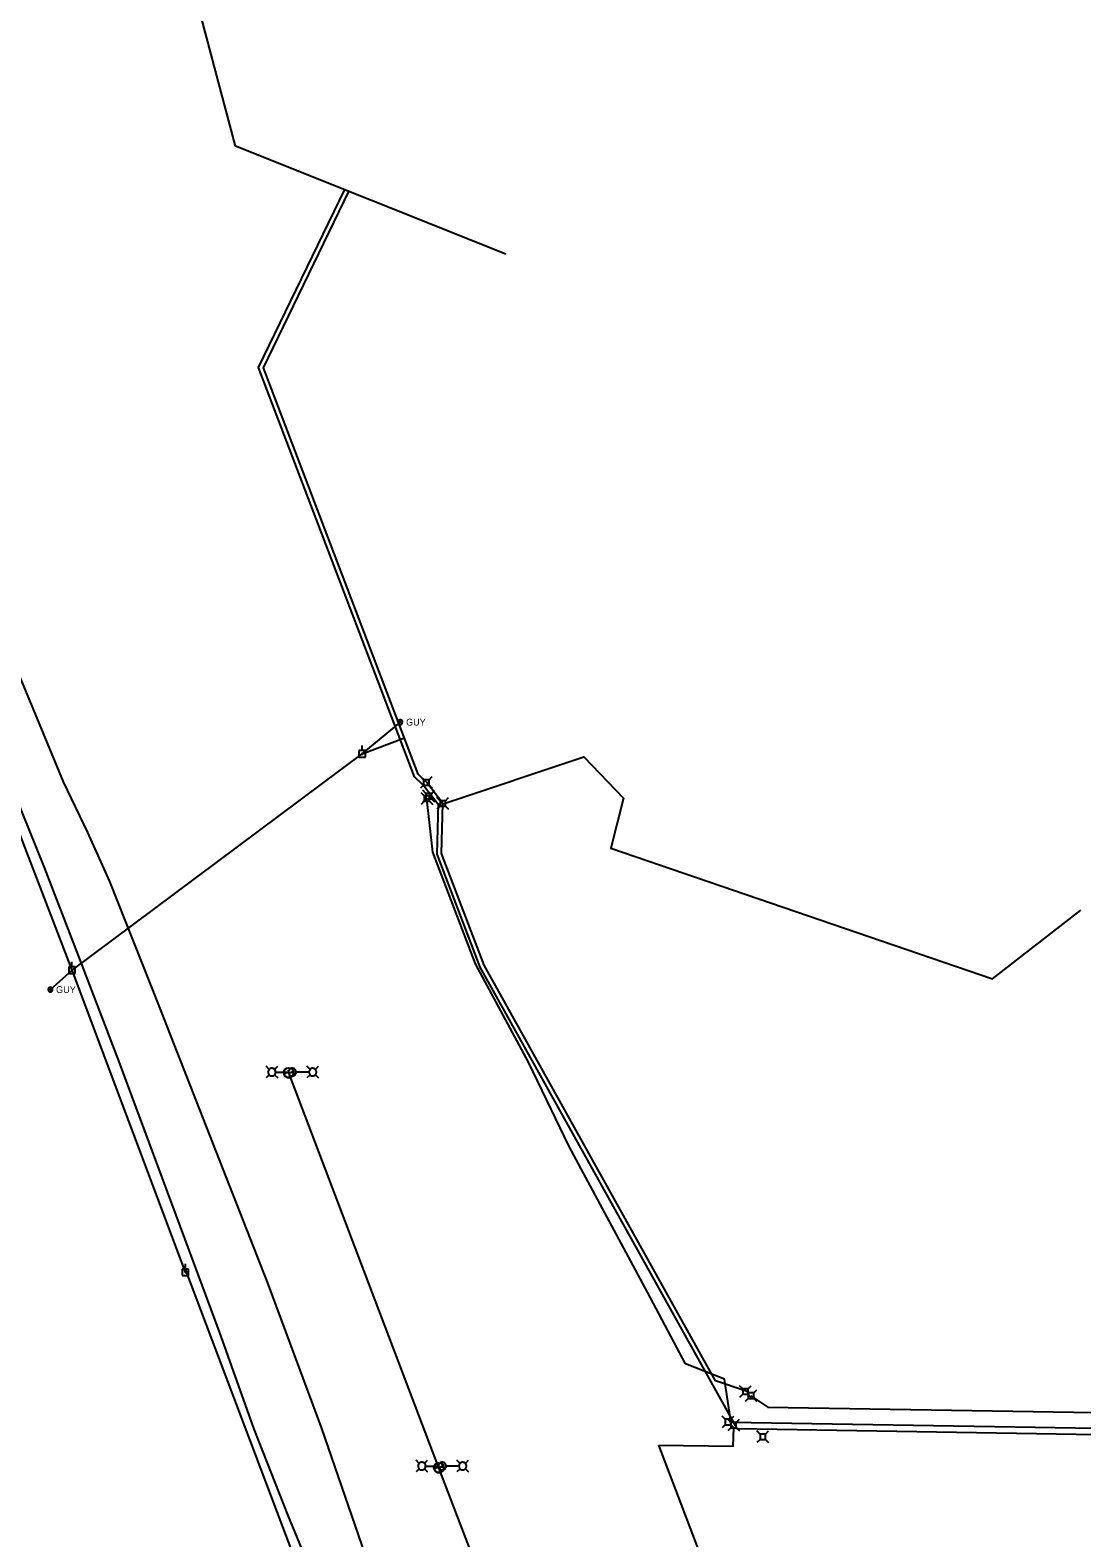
# Model space of a CAD drawing. Extents: x 596028 to 606371, y 330010 to 403088.
# Drawn here: x 603211 to 603807, y 351173 to 352028 of the extents above; entities that cross this region are included whole.
import ezdxf

# ---------------------------------------------------------------- set-up
doc = ezdxf.new("R2010")
doc.units = 0
for name, color, linetype in [('E_FTMS_Conduit', 7, 'Continuous'), ('E_LTG', 7, 'Continuous'), ('E_LTG_CID', 7, 'Continuous'), ('E_UTL_E', 7, 'Continuous'), ('E_UTL_E_UG', 7, 'Continuous'), ('E_UTL_EGuyWire', 7, 'Continuous'), ('E_UTL_EPowerPole', 7, 'Continuous'), ('E_UTL_FO_UG_QWEST', 7, 'Continuous'), ('E_UTL_Overhead', 7, 'Continuous'), ('E_UTL_T', 7, 'Continuous'), ('E_UTL_T_UG', 7, 'Continuous'), ('E_UTL_TV_UG', 7, 'Continuous')]:
    doc.layers.add(name, color=color, linetype=linetype)

# ---------------------------------------------------------------- blocks, each defined once
blk = doc.blocks.new('_U272')
at = {"layer": 'E_LTG'}
blk.add_lwpolyline([(0.001, -0.171), (0.001, 0.172)], dxfattribs=at)
blk.add_circle((0.001, 0), 0.171, dxfattribs=at)
blk.add_arc((0.001, 0), 0.171, 90, 270, dxfattribs=at)
blk.add_text('L', height=0.108, dxfattribs=at).set_placement((0.066, -0.042))

msp = doc.modelspace()

# ---------------------------------------------------------------- linework, layer by layer
at = {"layer": 'E_FTMS_Conduit'}
msp.add_lwpolyline([(603403.21, 351158.05), (603376.31, 351235.86), (603345.63, 351318.27), (603314.78, 351397.25), (603283.64, 351476.72), (603256.45, 351545.41), (603243.98, 351573.19), (603230.06, 351601.83), (603197.45, 351680.82), (603170.4, 351750.41), (603142.61, 351820.64), (603108.74, 351889.96), (603083.84, 351935.56), (603079.23, 351948.65), (603078.18, 351950.68), (603077.92, 351952.96), (603075.52, 351958.77), (603057.09, 352015.37), (603036.14, 352097.19)], dxfattribs=at)
at = {"layer": 'E_LTG'}
for points in [[(603346.66, 351438.81), (603344.88, 351440.59)], [(603346.66, 351435.76), (603344.88, 351433.99)], [(603350.36, 351437.29), (603350.32, 351437.7), (603350.2, 351438.1), (603350.01, 351438.46), (603349.76, 351438.79), (603349.44, 351439.06), (603349.09, 351439.27), (603348.69, 351439.4), (603348.29, 351439.46), (603347.87, 351439.44), (603347.47, 351439.34), (603347.09, 351439.17), (603346.76, 351438.93), (603346.47, 351438.63), (603346.25, 351438.29), (603346.09, 351437.9), (603346.02, 351437.5), (603346.02, 351437.08), (603346.09, 351436.68), (603346.25, 351436.29), (603346.47, 351435.94), (603346.76, 351435.64), (603347.09, 351435.4), (603347.47, 351435.23), (603347.87, 351435.14), (603348.29, 351435.12), (603348.69, 351435.17), (603349.09, 351435.31), (603349.44, 351435.52), (603349.76, 351435.79), (603350.01, 351436.11), (603350.2, 351436.48), (603350.32, 351436.88), (603350.36, 351437.29)], [(603349.7, 351438.81), (603351.48, 351440.59)], [(603349.7, 351435.76), (603351.48, 351433.99)], [(603350.39, 351437.29), (603357.57, 351437.29)], [(603361.92, 351437.29), (603361.88, 351437.7), (603361.77, 351438.1), (603361.58, 351438.46), (603361.32, 351438.79), (603361.01, 351439.06), (603360.65, 351439.27), (603360.26, 351439.4), (603359.85, 351439.46), (603359.44, 351439.44), (603359.04, 351439.34), (603358.66, 351439.17), (603358.32, 351438.93), (603358.04, 351438.63), (603357.81, 351438.29), (603357.66, 351437.9), (603357.58, 351437.49), (603357.58, 351437.08), (603357.66, 351436.68), (603357.81, 351436.29), (603358.04, 351435.94), (603358.32, 351435.64), (603358.66, 351435.4), (603359.04, 351435.23), (603359.44, 351435.13), (603359.85, 351435.12), (603360.26, 351435.17), (603360.65, 351435.31), (603361.01, 351435.52), (603361.32, 351435.79), (603361.58, 351436.11), (603361.77, 351436.48), (603361.88, 351436.88), (603361.92, 351437.29)], [(603359.91, 351437.29), (603359.91, 351437.32), (603359.9, 351437.35), (603359.89, 351437.38), (603359.87, 351437.4), (603359.84, 351437.42), (603359.82, 351437.44), (603359.79, 351437.45), (603359.76, 351437.45), (603359.72, 351437.45), (603359.69, 351437.45), (603359.66, 351437.43), (603359.64, 351437.41), (603359.62, 351437.39), (603359.6, 351437.36), (603359.59, 351437.34), (603359.58, 351437.3), (603359.58, 351437.27), (603359.59, 351437.24), (603359.6, 351437.21), (603359.62, 351437.19), (603359.64, 351437.16), (603359.66, 351437.14), (603359.69, 351437.13), (603359.72, 351437.12), (603359.76, 351437.12), (603359.79, 351437.13), (603359.82, 351437.14), (603359.84, 351437.15), (603359.87, 351437.17), (603359.89, 351437.2), (603359.9, 351437.23), (603359.91, 351437.26), (603359.91, 351437.29)], [(603369.14, 351437.29), (603361.96, 351437.29)], [(603369.83, 351438.81), (603368.05, 351440.59)], [(603369.83, 351435.77), (603368.05, 351433.99)], [(603373.53, 351437.29), (603373.49, 351437.7), (603373.37, 351438.1), (603373.18, 351438.46), (603372.92, 351438.79), (603372.61, 351439.06), (603372.25, 351439.27), (603371.86, 351439.4), (603371.45, 351439.46), (603371.04, 351439.44), (603370.64, 351439.34), (603370.26, 351439.17), (603369.93, 351438.93), (603369.64, 351438.63), (603369.42, 351438.29), (603369.26, 351437.9), (603369.18, 351437.49), (603369.18, 351437.08), (603369.26, 351436.68), (603369.42, 351436.29), (603369.64, 351435.94), (603369.93, 351435.64), (603370.26, 351435.4), (603370.64, 351435.23), (603371.04, 351435.13), (603371.45, 351435.12), (603371.86, 351435.17), (603372.25, 351435.31), (603372.61, 351435.52), (603372.92, 351435.79), (603373.18, 351436.11), (603373.37, 351436.48), (603373.49, 351436.88), (603373.53, 351437.29)], [(603372.88, 351438.81), (603374.65, 351440.59)], [(603372.88, 351435.77), (603374.65, 351433.99)], [(603431.64, 351215.51), (603429.87, 351217.29)], [(603431.64, 351212.46), (603429.87, 351210.69)], [(603435.34, 351213.99), (603435.3, 351214.4), (603435.19, 351214.8), (603435, 351215.17), (603434.74, 351215.49), (603434.43, 351215.76), (603434.07, 351215.97), (603433.68, 351216.1), (603433.27, 351216.16), (603432.86, 351216.14), (603432.45, 351216.04), (603432.08, 351215.87), (603431.74, 351215.63), (603431.46, 351215.33), (603431.23, 351214.99), (603431.08, 351214.6), (603431, 351214.2), (603431, 351213.78), (603431.08, 351213.38), (603431.23, 351212.99), (603431.46, 351212.64), (603431.74, 351212.34), (603432.08, 351212.1), (603432.45, 351211.93), (603432.86, 351211.84), (603433.27, 351211.82), (603433.68, 351211.87), (603434.07, 351212.01), (603434.43, 351212.22), (603434.74, 351212.49), (603435, 351212.81), (603435.19, 351213.18), (603435.3, 351213.58), (603435.34, 351213.99)], [(603434.69, 351215.51), (603436.47, 351217.29)], [(603434.69, 351212.46), (603436.47, 351210.69)], [(603435.38, 351213.99), (603442.56, 351213.99)], [(603446.91, 351213.99), (603446.87, 351214.4), (603446.75, 351214.8), (603446.56, 351215.16), (603446.31, 351215.49), (603445.99, 351215.76), (603445.64, 351215.97), (603445.25, 351216.1), (603444.84, 351216.16), (603444.42, 351216.14), (603444.02, 351216.04), (603443.64, 351215.87), (603443.31, 351215.63), (603443.02, 351215.33), (603442.8, 351214.99), (603442.64, 351214.6), (603442.57, 351214.2), (603442.57, 351213.78), (603442.64, 351213.38), (603442.8, 351212.99), (603443.02, 351212.64), (603443.31, 351212.34), (603443.64, 351212.1), (603444.02, 351211.93), (603444.42, 351211.84), (603444.84, 351211.82), (603445.25, 351211.87), (603445.64, 351212.01), (603445.99, 351212.22), (603446.31, 351212.49), (603446.56, 351212.81), (603446.75, 351213.18), (603446.87, 351213.58), (603446.91, 351213.99)], [(603444.9, 351213.99), (603444.9, 351214.02), (603444.89, 351214.05), (603444.87, 351214.08), (603444.85, 351214.1), (603444.83, 351214.12), (603444.8, 351214.14), (603444.77, 351214.15), (603444.74, 351214.15), (603444.71, 351214.15), (603444.68, 351214.15), (603444.65, 351214.13), (603444.62, 351214.11), (603444.6, 351214.09), (603444.58, 351214.06), (603444.57, 351214.04), (603444.57, 351214), (603444.57, 351213.97), (603444.57, 351213.94), (603444.58, 351213.91), (603444.6, 351213.89), (603444.62, 351213.86), (603444.65, 351213.84), (603444.68, 351213.83), (603444.71, 351213.82), (603444.74, 351213.82), (603444.77, 351213.83), (603444.8, 351213.84), (603444.83, 351213.85), (603444.85, 351213.87), (603444.87, 351213.9), (603444.89, 351213.93), (603444.9, 351213.96), (603444.9, 351213.99)], [(603454.12, 351213.99), (603446.94, 351213.99)], [(603454.81, 351215.51), (603453.04, 351217.29)], [(603454.81, 351212.47), (603453.04, 351210.69)], [(603458.51, 351213.99), (603458.47, 351214.4), (603458.35, 351214.8), (603458.17, 351215.16), (603457.91, 351215.49), (603457.6, 351215.76), (603457.24, 351215.97), (603456.85, 351216.1), (603456.44, 351216.16), (603456.03, 351216.14), (603455.62, 351216.04), (603455.25, 351215.87), (603454.91, 351215.63), (603454.62, 351215.33), (603454.4, 351214.99), (603454.25, 351214.6), (603454.17, 351214.2), (603454.17, 351213.78), (603454.25, 351213.38), (603454.4, 351212.99), (603454.62, 351212.64), (603454.91, 351212.34), (603455.25, 351212.1), (603455.62, 351211.93), (603456.03, 351211.84), (603456.44, 351211.82), (603456.85, 351211.87), (603457.24, 351212.01), (603457.6, 351212.22), (603457.91, 351212.49), (603458.17, 351212.81), (603458.35, 351213.18), (603458.47, 351213.58), (603458.51, 351213.99)], [(603457.86, 351215.51), (603459.64, 351217.29)], [(603457.86, 351212.47), (603459.64, 351210.69)]]:
    msp.add_lwpolyline(points, dxfattribs=at)
at = {"layer": 'E_LTG_CID'}
for points in [[(603357.76, 351436.96), (603359.75, 351437.29)], [(604318.05, 348339.7), (604287.36, 348606.91), (604242.16, 348872.6), (604188.57, 349120.13), (604125.01, 349362.84), (604050.82, 349602.08), (604014.23, 349708.06), (603966.43, 349837.54), (603869.82, 350091.09), (603838.85, 350172.22), (603784.41, 350315.72), (603699.29, 350539.43), (603613.87, 350764.2), (603510.34, 351036.54), (603442.84, 351213.06), (603357.76, 351436.96)], [(603442.84, 351213.06), (603444.73, 351213.99)]]:
    msp.add_lwpolyline(points, dxfattribs=at)
at = {"layer": 'E_UTL_E'}
for points in [[(603434.2, 351603.04), (603432.45, 351604.79)], [(603434.2, 351599.94), (603432.45, 351598.19)], [(603437.3, 351603.04), (603434.2, 351603.04)], [(603434.2, 351603.04), (603434.2, 351599.94)], [(603434.2, 351599.94), (603437.3, 351599.94)], [(603437.3, 351603.04), (603439.05, 351604.79)], [(603437.3, 351599.94), (603437.3, 351603.04)], [(603437.3, 351599.94), (603439.05, 351598.19)], [(603443.51, 351591.11), (603441.76, 351592.86)], [(603446.61, 351591.11), (603443.51, 351591.11)], [(603443.51, 351591.11), (603443.51, 351588.01)], [(603446.61, 351591.11), (603448.36, 351592.86)], [(603446.61, 351588.01), (603446.61, 351591.11)], [(603443.51, 351588.01), (603441.76, 351586.26)], [(603443.51, 351588.01), (603446.61, 351588.01)], [(603446.61, 351588.01), (603448.36, 351586.26)], [(603615.01, 351257.76), (603613.26, 351259.51)], [(603618.11, 351257.76), (603615.01, 351257.76)], [(603615.01, 351257.76), (603615.01, 351254.67)], [(603618.14, 351255.47), (603616.38, 351257.22)], [(603618.11, 351257.76), (603619.86, 351259.51)], [(603618.11, 351254.67), (603618.11, 351257.76)], [(603621.23, 351255.47), (603618.14, 351255.47)], [(603618.14, 351255.47), (603618.14, 351252.37)], [(603621.23, 351255.47), (603622.98, 351257.22)], [(603621.23, 351252.37), (603621.23, 351255.47)], [(603615.01, 351254.67), (603613.26, 351252.91)], [(603615.01, 351254.67), (603618.11, 351254.67)], [(603618.14, 351252.37), (603616.38, 351250.62)], [(603618.11, 351254.67), (603619.86, 351252.91)], [(603618.14, 351252.37), (603621.23, 351252.37)], [(603621.23, 351252.37), (603622.98, 351250.62)]]:
    msp.add_lwpolyline(points, dxfattribs=at)
at = {"layer": 'E_UTL_E_UG'}
msp.add_line((603399.4, 351617.73), (603423.29, 351626.83), dxfattribs=at)
for points in [[(603480.85, 351900.95), (603327.53, 351962.1), (603296.88, 352078.37), (603383.86, 352114.9)], [(603445.15, 351589.5), (603435.76, 351601.62), (603431.17, 351606.14), (603343.42, 351836.48), (603391.85, 351936.45)], [(603445.21, 351589.3), (603525.03, 351615.94), (603547.54, 351592.55), (603540.25, 351564.2), (603756.64, 351490.08), (603806.69, 351529)], [(603616.87, 351256.36), (603599.55, 351262.39), (603468.47, 351497.89), (603444.33, 351561.26), (603445.15, 351589.5)], [(603619.57, 351253.84), (603629.29, 351247.41), (604265.3, 351237.02)]]:
    msp.add_lwpolyline(points, dxfattribs=at)
at = {"layer": 'E_UTL_EGuyWire'}
for p, q in [((603399.4, 351617.73), (603421.03, 351635.67)), ((603222.7, 351484.07), (603234.96, 351495.08))]:
    msp.add_line(p, q, dxfattribs=at)
for points in [[(603422.31, 351635.67), (603422.29, 351635.91), (603422.22, 351636.15), (603422.11, 351636.36), (603421.96, 351636.55), (603421.77, 351636.71), (603421.56, 351636.84), (603421.33, 351636.92), (603421.09, 351636.95), (603420.85, 351636.94), (603420.61, 351636.88), (603420.39, 351636.78), (603420.19, 351636.64), (603420.02, 351636.46), (603419.89, 351636.26), (603419.8, 351636.03), (603419.75, 351635.79), (603419.75, 351635.55), (603419.8, 351635.31), (603419.89, 351635.08), (603420.02, 351634.88), (603420.19, 351634.7), (603420.39, 351634.56), (603420.61, 351634.46), (603420.85, 351634.4), (603421.09, 351634.39), (603421.33, 351634.42), (603421.56, 351634.5), (603421.77, 351634.62), (603421.96, 351634.78), (603422.11, 351634.98), (603422.22, 351635.19), (603422.29, 351635.43), (603422.31, 351635.67)], [(603421.19, 351635.67), (603421.19, 351635.7), (603421.18, 351635.73), (603421.16, 351635.76), (603421.15, 351635.78), (603421.12, 351635.8), (603421.1, 351635.81), (603421.07, 351635.82), (603421.04, 351635.83), (603421.01, 351635.83), (603420.98, 351635.82), (603420.95, 351635.81), (603420.92, 351635.79), (603420.9, 351635.77), (603420.89, 351635.74), (603420.88, 351635.71), (603420.87, 351635.68), (603420.87, 351635.65), (603420.88, 351635.62), (603420.89, 351635.6), (603420.9, 351635.57), (603420.92, 351635.55), (603420.95, 351635.53), (603420.98, 351635.52), (603421.01, 351635.51), (603421.04, 351635.51), (603421.07, 351635.51), (603421.1, 351635.52), (603421.12, 351635.54), (603421.15, 351635.56), (603421.16, 351635.58), (603421.18, 351635.61), (603421.19, 351635.64), (603421.19, 351635.67)], [(603223.98, 351484.07), (603223.96, 351484.31), (603223.89, 351484.54), (603223.78, 351484.76), (603223.63, 351484.95), (603223.44, 351485.11), (603223.23, 351485.23), (603223, 351485.31), (603222.76, 351485.35), (603222.52, 351485.34), (603222.28, 351485.28), (603222.06, 351485.18), (603221.86, 351485.04), (603221.69, 351484.86), (603221.56, 351484.66), (603221.47, 351484.43), (603221.42, 351484.19), (603221.42, 351483.95), (603221.47, 351483.71), (603221.56, 351483.48), (603221.69, 351483.27), (603221.86, 351483.1), (603222.06, 351482.96), (603222.28, 351482.85), (603222.52, 351482.8), (603222.76, 351482.79), (603223, 351482.82), (603223.23, 351482.9), (603223.44, 351483.02), (603223.63, 351483.18), (603223.78, 351483.37), (603223.89, 351483.59), (603223.96, 351483.82), (603223.98, 351484.07)], [(603222.86, 351484.07), (603222.86, 351484.1), (603222.85, 351484.13), (603222.83, 351484.15), (603222.82, 351484.18), (603222.79, 351484.2), (603222.77, 351484.21), (603222.74, 351484.22), (603222.71, 351484.23), (603222.68, 351484.23), (603222.65, 351484.22), (603222.62, 351484.21), (603222.59, 351484.19), (603222.57, 351484.17), (603222.56, 351484.14), (603222.55, 351484.11), (603222.54, 351484.08), (603222.54, 351484.05), (603222.55, 351484.02), (603222.56, 351483.99), (603222.57, 351483.97), (603222.59, 351483.95), (603222.62, 351483.93), (603222.65, 351483.92), (603222.68, 351483.91), (603222.71, 351483.91), (603222.74, 351483.91), (603222.77, 351483.92), (603222.79, 351483.94), (603222.82, 351483.96), (603222.83, 351483.98), (603222.85, 351484.01), (603222.86, 351484.04), (603222.86, 351484.07)]]:
    msp.add_lwpolyline(points, dxfattribs=at)
at = {"layer": 'E_UTL_EPowerPole'}
for points in [[(603399.36, 351619.57), (603399.36, 351622.48)], [(603401.21, 351619.57), (603397.52, 351619.57)], [(603397.52, 351619.57), (603397.52, 351615.88)], [(603397.52, 351615.88), (603401.21, 351615.88)], [(603399.64, 351617.73), (603399.63, 351617.77), (603399.62, 351617.82), (603399.6, 351617.86), (603399.57, 351617.89), (603399.54, 351617.92), (603399.5, 351617.94), (603399.45, 351617.96), (603399.41, 351617.97), (603399.36, 351617.96), (603399.32, 351617.95), (603399.28, 351617.93), (603399.24, 351617.91), (603399.21, 351617.88), (603399.19, 351617.84), (603399.17, 351617.8), (603399.16, 351617.75), (603399.16, 351617.71), (603399.17, 351617.66), (603399.19, 351617.62), (603399.21, 351617.58), (603399.24, 351617.55), (603399.28, 351617.52), (603399.32, 351617.5), (603399.36, 351617.49), (603399.41, 351617.49), (603399.45, 351617.5), (603399.5, 351617.51), (603399.54, 351617.53), (603399.57, 351617.56), (603399.6, 351617.6), (603399.62, 351617.64), (603399.63, 351617.68), (603399.64, 351617.73)], [(603401.21, 351615.88), (603401.21, 351619.57)], [(603236.77, 351496.92), (603233.08, 351496.92)], [(603233.08, 351496.92), (603233.08, 351493.23)], [(603235.19, 351495.08), (603235.19, 351495.13), (603235.18, 351495.17), (603235.16, 351495.21), (603235.13, 351495.25), (603235.09, 351495.28), (603235.06, 351495.3), (603235.01, 351495.31), (603234.97, 351495.32), (603234.92, 351495.32), (603234.88, 351495.31), (603234.84, 351495.29), (603234.8, 351495.26), (603234.77, 351495.23), (603234.74, 351495.19), (603234.73, 351495.15), (603234.72, 351495.1), (603234.72, 351495.06), (603234.73, 351495.01), (603234.74, 351494.97), (603234.77, 351494.93), (603234.8, 351494.9), (603234.84, 351494.88), (603234.88, 351494.86), (603234.92, 351494.85), (603234.97, 351494.84), (603235.01, 351494.85), (603235.06, 351494.87), (603235.09, 351494.89), (603235.13, 351494.92), (603235.16, 351494.95), (603235.18, 351494.99), (603235.19, 351495.04), (603235.19, 351495.08)], [(603234.92, 351496.92), (603234.92, 351499.83)], [(603236.77, 351493.23), (603236.77, 351496.92)], [(603233.08, 351493.23), (603236.77, 351493.23)], [(603301.03, 351325.68), (603297.35, 351325.68)], [(603297.35, 351325.68), (603297.35, 351321.99)], [(603299.46, 351323.84), (603299.46, 351323.89), (603299.44, 351323.93), (603299.42, 351323.97), (603299.39, 351324.01), (603299.36, 351324.04), (603299.32, 351324.06), (603299.28, 351324.07), (603299.23, 351324.08), (603299.19, 351324.08), (603299.14, 351324.07), (603299.1, 351324.05), (603299.07, 351324.02), (603299.03, 351323.99), (603299.01, 351323.95), (603298.99, 351323.91), (603298.98, 351323.86), (603298.98, 351323.82), (603298.99, 351323.77), (603299.01, 351323.73), (603299.03, 351323.69), (603299.07, 351323.66), (603299.1, 351323.63), (603299.14, 351323.62), (603299.19, 351323.6), (603299.23, 351323.6), (603299.28, 351323.61), (603299.32, 351323.62), (603299.36, 351323.65), (603299.39, 351323.68), (603299.42, 351323.71), (603299.44, 351323.75), (603299.46, 351323.8), (603299.46, 351323.84)], [(603299.19, 351325.68), (603299.19, 351328.59)], [(603301.03, 351321.99), (603301.03, 351325.68)], [(603297.35, 351321.99), (603301.03, 351321.99)]]:
    msp.add_lwpolyline(points, dxfattribs=at)
at = {"layer": 'E_UTL_FO_UG_QWEST'}
msp.add_lwpolyline([(603379.61, 351132.32), (603357.48, 351186), (603338.12, 351234.94), (603318.47, 351290.15), (603261.54, 351443.61), (603240.69, 351497.96), (603219.41, 351553.26), (603202.31, 351595.31), (603193.02, 351622.62), (603180.64, 351650.84), (603160.01, 351705.33), (603141.78, 351751.1), (603123.96, 351797.78), (603092.33, 351873.51), (603071.51, 351941.92), (603018.75, 352078.03)], dxfattribs=at)
at = {"layer": 'E_UTL_Overhead'}
for p, q in [((603234.96, 351495.08), (603399.4, 351617.73)), ((603299.22, 351323.84), (603234.96, 351495.08))]:
    msp.add_line(p, q, dxfattribs=at)
for points in [[(603234.96, 351495.08), (603169.95, 351663.72), (603105.51, 351833.01), (603040.21, 352003.72), (602976.48, 352171.6), (602911.48, 352341.94), (602848.09, 352509.68), (602786.89, 352671.3)], [(603468.46, 350246.59), (603449.86, 350441.98), (603456.5, 350830.83), (603431.88, 350974.54), (603298.9, 351326.49)]]:
    msp.add_lwpolyline(points, dxfattribs=at)
at = {"layer": 'E_UTL_T'}
for points in [[(603435.47, 351595.28), (603433.72, 351597.04)], [(603438.56, 351595.28), (603440.32, 351597.04)], [(603434.48, 351593.92), (603432.73, 351595.67)], [(603434.48, 351590.82), (603432.73, 351589.07)], [(603435.47, 351592.19), (603433.72, 351590.44)], [(603437.58, 351593.92), (603434.48, 351593.92)], [(603434.48, 351593.92), (603434.48, 351590.82)], [(603434.48, 351590.82), (603437.58, 351590.82)], [(603438.56, 351595.28), (603435.47, 351595.28)], [(603435.47, 351595.28), (603435.47, 351592.19)], [(603435.47, 351592.19), (603438.56, 351592.19)], [(603437.58, 351593.92), (603439.33, 351595.67)], [(603437.58, 351590.82), (603437.58, 351593.92)], [(603437.58, 351590.82), (603439.33, 351589.07)], [(603438.56, 351592.19), (603438.56, 351595.28)], [(603438.56, 351592.19), (603440.32, 351590.44)], [(603605.09, 351240.48), (603603.34, 351242.24)], [(603608.18, 351240.48), (603605.09, 351240.48)], [(603605.09, 351240.48), (603605.09, 351237.39)], [(603608.24, 351238.76), (603606.49, 351240.51)], [(603608.18, 351240.48), (603609.94, 351242.24)], [(603608.18, 351237.39), (603608.18, 351240.48)], [(603611.34, 351238.76), (603608.24, 351238.76)], [(603608.24, 351238.76), (603608.24, 351235.66)], [(603611.34, 351238.76), (603613.09, 351240.51)], [(603611.34, 351235.66), (603611.34, 351238.76)], [(603605.09, 351237.39), (603603.34, 351235.64)], [(603605.09, 351237.39), (603608.18, 351237.39)], [(603608.24, 351235.66), (603606.49, 351233.91)], [(603608.18, 351237.39), (603609.94, 351235.64)], [(603608.24, 351235.66), (603611.34, 351235.66)], [(603611.34, 351235.66), (603613.09, 351233.91)], [(603624.81, 351232.16), (603623.06, 351233.91)], [(603627.91, 351232.16), (603624.81, 351232.16)], [(603624.81, 351232.16), (603624.81, 351229.07)], [(603627.91, 351232.16), (603629.66, 351233.91)], [(603627.91, 351229.07), (603627.91, 351232.16)], [(603624.81, 351229.07), (603623.06, 351227.31)], [(603624.81, 351229.07), (603627.91, 351229.07)], [(603627.91, 351229.07), (603629.66, 351227.31)]]:
    msp.add_lwpolyline(points, dxfattribs=at)
at = {"layer": 'E_UTL_T_UG'}
for p, q in [((603608.24, 351238.94), (604107.79, 351230.77)), ((603783.02, 350660.08), (603567.46, 351225.92))]:
    msp.add_line(p, q, dxfattribs=at)
for points in [[(603463.54, 351498.66), (603439.46, 351561.87), (603435.95, 351592.23)], [(603582.64, 351271.87), (603561.08, 351312.47), (603516.61, 351395.05), (603493.61, 351443.02), (603463.53, 351498.66)], [(603608.42, 351238.22), (603604.61, 351263.24), (603582.64, 351271.87)], [(603567.46, 351225.92), (603609.62, 351225.23), (603609.94, 351235.64)]]:
    msp.add_lwpolyline(points, dxfattribs=at)
at = {"layer": 'E_UTL_TV_UG'}
msp.add_line((603611.82, 351235.19), (604010.13, 351228.69), dxfattribs=at)
for points in [[(603443.17, 351587.97), (603433.88, 351599.96), (603429.02, 351604.75), (603340.7, 351836.6), (603389.6, 351937.54)], [(603611.82, 351235.19), (603466.19, 351496.84), (603441.81, 351560.83), (603442.65, 351589.57)]]:
    msp.add_lwpolyline(points, dxfattribs=at)

# ---------------------------------------------------------------- block references
at = {"layer": 'E_LTG_CID', "xscale": 16.404166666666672, "yscale": 16.404166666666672, "rotation": 97.82095686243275}
for p in [(603357.76, 351436.95), (603442.85, 351213.05)]:
    msp.add_blockref('_U272', p, dxfattribs=at)

# ---------------------------------------------------------------- texts
at = {"layer": 'E_UTL_EGuyWire'}
for p in [(603424.24, 351633.74), (603225.91, 351482.14)]:
    msp.add_text('GUY', height=3.85, dxfattribs=at).set_placement(p)

doc.saveas('drawing.dxf')
